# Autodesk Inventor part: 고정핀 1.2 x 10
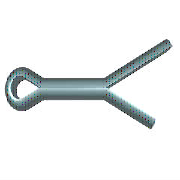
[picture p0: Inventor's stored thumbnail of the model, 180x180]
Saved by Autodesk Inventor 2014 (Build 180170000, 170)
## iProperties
IsCustomPart: 1
Created: 2012-02
Part Number: 고정핀 1.2 x 10
Material: 강철
Description: 분할 핀
Document SubType Name: Modeling
Standard: ISO 1234
Designer: test
Standard Revision: Second edition 1997-11-01
Standards Organization: ISO
Language: ko-KR
Size Designation: 1.2 x 10
Categories: <MemberInstance><Categories><Category DisplayName="조임쇠" InternalName="e4da775c-781d-43d5-af7c-5136215cf5a6" Mnemonic="FSTN"><Category DisplayName="핀" InternalNa
Density: 7.85 g/cm^3
Appearance: 강철
Author: test
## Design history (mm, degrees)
sketch "스케치1"
  geometry: L1 (0, 0.5)-(5, 0.5); L2 (0, -0.5)-(5, -0.5); L3 (5, 0.5)-(10, 2.416); L4 (10, 2.416)-(10.167, 1.98); L5 (10.167, 1.98)-(5, 0); L6 (5, 0)-(12.667, -2.937); L7 (12.667, -2.937)-(12.5, -3.373); L8 (12.5, -3.373)-(5, -0.5); L9 (0, 0)-(-1.875, -0.484); L10 (0, 0)-(-1.875, 0.484); L11 (0, 0.5)-(0, -0.5); L12 (0, 0.5)-(-1.742, 0.966); L13 (0, -0.5)-(-1.742, -0.966); L14 (-3, 0)-(5, 0); L15 (5, 0.5)-(5, -0.5); A1 r 1 centre (-2, 0) between (-1.742, 0.966) and (-1.742, -0.966); A2 r 0.5 centre (-2, 0) between (-1.875, 0.484) and (-1.875, -0.484); 1 further point
  constraints: 30 end point, 5 point on circle, 4 parallel, 4 perpendicular, 4 point on line, 4 tangent, 2 centre point, 2 midpoint, 1 coincident, 1 horizontal
  dimensions: "d0" = 5 distance of L1.start L1.end (= MSIAB); "d1" = 10 horizontal distance of L1.start L3.end (= SNLG); "d2" = 159.037 deg angle of L1 L3; "d3" = 159.037 deg angle of L2 L8; "d4" = 2.5 horizontal distance of L3.end L7.end (= LGDIF); "d5" = 0.5 radius of A2 (= -0.5 x SNND1 + 0.5 x KBR); "d6" = 1 radius of A1 (= 0.5 x KBR); "d7" = 0.5 distance from line of L1 L9.start (= 0.5 x SNND1); "d8" = 0.5 distance between parallel lines of L2 L14 (= 0.5 x SNND1); "d9" = 2 distance from line of L11 A1.centre (= KOL - 0.5 x KBR)
extrude "본체" new body sketch "스케치1" stored distance "d10" = 1 (= SNND1); taper "d11" = 0 deg
workaxis "Work Axis1"
workplane "Work Plane1"
workplane "Work Plane3"
body "Solid1"
fillet "모깎기" dims "d12" = 0.35 (= 0.35 x SNND1)
other parameters: "SNND" = 1.2 [user parameter], "SNLG" = 10 [user parameter; used in 1 equation term], "SNND1" = 1 [user parameter; used in 5 equation terms], "KBR" = 2 [user parameter; used in 3 equation terms], "KOL" = 3 [user parameter; used in 1 equation term], "LGDIF" = 2.5 [user parameter; used in 1 equation term], "MSIAB" = 5 [user parameter; used in 1 equation term], "d15" = 0, "d16" = 0, "d17" = 0, "NNDMAX" = 5.5 [user parameter], "DSH" = 2.6 [user parameter], "NNDMIN" = 4.5 [user parameter]
